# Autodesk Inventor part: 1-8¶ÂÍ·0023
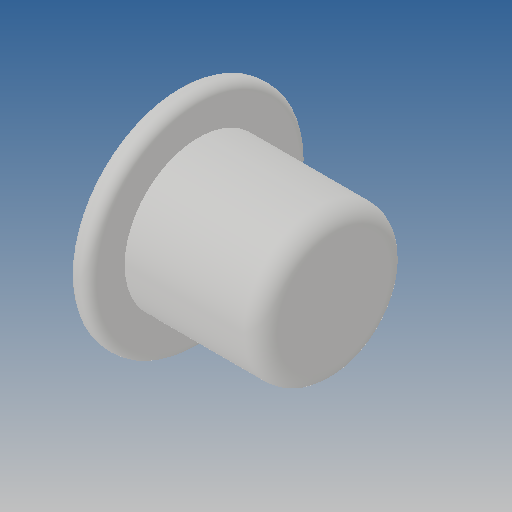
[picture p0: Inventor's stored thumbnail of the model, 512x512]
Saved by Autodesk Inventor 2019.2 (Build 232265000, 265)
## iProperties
Created: 2013-09
Part Number: 1-8¶ÂÍ·0023
Material: Ogólny
Document SubType Name: Modeling
Designer: CADENGINEERING4
Density: 1 g/cm^3
Appearance: Domyślna
Author: CADENGINEERING4
Revision Number: ÈÎºÎ
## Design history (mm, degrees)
feature "Ô²½Ç1"
node "Bryła1"
